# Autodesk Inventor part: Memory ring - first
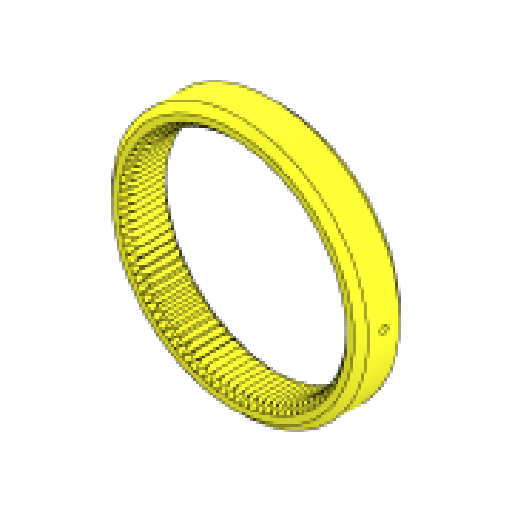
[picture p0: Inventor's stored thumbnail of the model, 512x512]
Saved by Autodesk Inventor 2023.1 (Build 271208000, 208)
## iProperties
Created: 2020-02
Part Number: Memory ring - first
Material: Generic
Document SubType Name: Modeling
Designer: ftrauzettel
Density: 1 g/cm^3
Appearance: Default
Sending System: SolidWorks 2016
Last Author: Pam
Last Saved: 2020-07-17
Author: ftrauzettel
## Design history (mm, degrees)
feature "CirPattern1"
body "Solid1"
